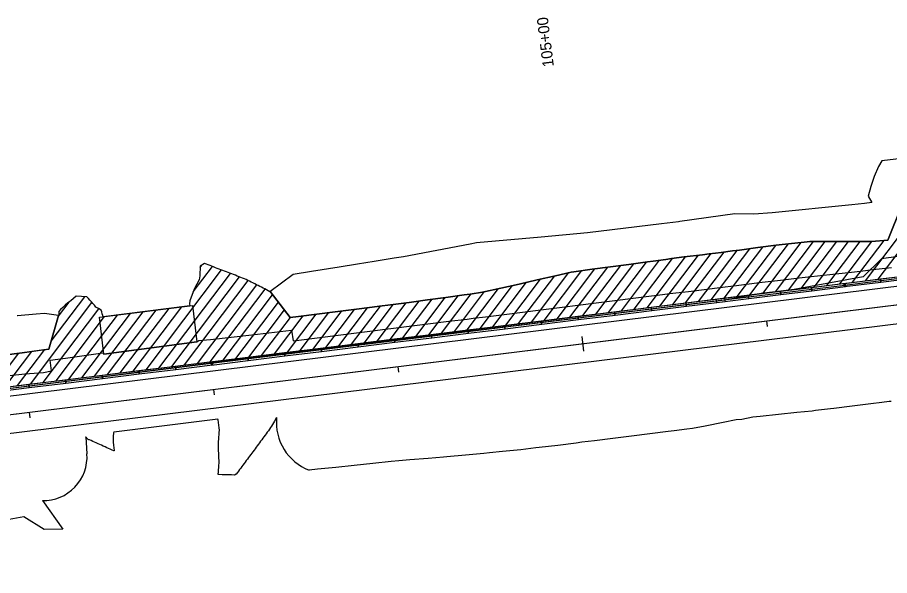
# Model space of a CAD drawing. Extents: x 1568809 to 1572786, y 728326 to 734907.
# Drawn here: x 1570478.4 to 1570947.9, y 732119 to 732419.2 of the extents above; entities that cross this region are included whole.
import ezdxf

# ---------------------------------------------------------------- set-up
doc = ezdxf.new("R2010")
doc.units = 0
for name, color, linetype in [('R_Horz Alg', 7, 'Continuous'), ('R_Horz Alg Annot', 7, 'Continuous'), ('R_MOT', 7, 'Continuous'), ('R_No Plot', 7, 'Continuous'), ('R_Striping', 7, 'Continuous')]:
    doc.layers.add(name, color=color, linetype=linetype)

msp = doc.modelspace()

# ---------------------------------------------------------------- linework, layer by layer
at = {"layer": 'R_Horz Alg'}
msp.add_line((1569774.69, 732119.01), (1571082.41, 732280.73), dxfattribs=at)
at = {"layer": 'R_Horz Alg Annot'}
for points in [[(1570882.23, 732252.95), (1570881.86, 732255.93)], [(1570782.13, 732247.63), (1570783.11, 732239.69)], [(1570683.74, 732228.41), (1570683.37, 732231.38)], [(1570584.5, 732216.13), (1570584.13, 732219.11)], [(1570485.25, 732203.86), (1570484.88, 732206.84)]]:
    msp.add_lwpolyline(points, dxfattribs=at)
at = {"layer": 'R_MOT'}
for p, q in [((1570934.91, 732277.61), (1570977.23, 732333.54)), ((1570941.83, 732278.46), (1570984.39, 732334.72)), ((1570851.91, 732267.34), (1570872.7, 732294.82)), ((1570858.83, 732268.2), (1570879.65, 732295.72)), ((1570865.75, 732269.05), (1570886.59, 732296.61)), ((1570872.66, 732269.91), (1570893.46, 732297.39)), ((1570879.58, 732270.76), (1570900.29, 732298.14)), ((1570886.5, 732271.62), (1570906.93, 732298.63)), ((1570893.41, 732272.47), (1570913.19, 732298.62)), ((1570900.33, 732273.33), (1570919.45, 732298.6)), ((1570907.25, 732274.19), (1570925.72, 732298.6)), ((1570914.16, 732275.04), (1570932, 732298.61)), ((1570921.08, 732275.9), (1570938.29, 732298.64)), ((1570928, 732276.75), (1570945.04, 732299.27)), ((1570817.33, 732263.07), (1570838.05, 732290.45)), ((1570824.25, 732263.92), (1570844.96, 732291.3)), ((1570831.16, 732264.78), (1570851.88, 732292.17)), ((1570838.08, 732265.63), (1570858.81, 732293.03)), ((1570845, 732266.49), (1570865.75, 732293.92)), ((1570572.97, 732271.56), (1570583.32, 732285.24)), ((1570576.69, 732284.75), (1570577.63, 732286)), ((1570782.75, 732258.79), (1570803.17, 732285.78)), ((1570789.66, 732259.64), (1570810.14, 732286.7)), ((1570796.58, 732260.5), (1570817.11, 732287.64)), ((1570803.5, 732261.35), (1570824.1, 732288.58)), ((1570810.41, 732262.21), (1570831.09, 732289.54)), ((1570547.58, 732229.71), (1570588.18, 732283.37)), ((1570554.5, 732230.56), (1570593.05, 732281.52)), ((1570755.08, 732255.37), (1570775.19, 732281.94)), ((1570762, 732256.22), (1570782.29, 732283.04)), ((1570768.91, 732257.08), (1570789.27, 732283.98)), ((1570775.83, 732257.93), (1570796.21, 732284.87)), ((1570561.42, 732231.42), (1570597.9, 732279.64)), ((1570568.33, 732232.27), (1570602.65, 732277.63)), ((1570734.33, 732252.8), (1570752.44, 732276.74)), ((1570741.25, 732253.66), (1570760.02, 732278.46)), ((1570748.17, 732254.51), (1570767.6, 732280.21)), ((1570575.25, 732233.13), (1570607.19, 732275.35)), ((1570582.17, 732233.98), (1570611.74, 732273.08)), ((1570713.58, 732250.23), (1570729.83, 732271.71)), ((1570720.5, 732251.09), (1570737.32, 732273.32)), ((1570727.42, 732251.95), (1570744.87, 732275.02)), ((1570898.53, 732273.11), (1570878.68, 732270.65)), ((1570496.52, 732245.08), (1570514.57, 732268.95)), ((1570858.95, 732267.21), (1570582.41, 732233.01)), ((1570589.08, 732234.84), (1570615.74, 732270.07)), ((1570679, 732245.96), (1570694.66, 732266.66)), ((1570685.92, 732246.81), (1570701.64, 732267.6)), ((1570692.83, 732247.67), (1570708.63, 732268.55)), ((1570699.75, 732248.52), (1570715.62, 732269.51)), ((1570706.67, 732249.38), (1570722.64, 732270.5)), ((1570878.68, 732270.65), (1570858.95, 732267.21)), ((1570485.33, 732222.01), (1570518.48, 732265.82)), ((1570492.25, 732222.86), (1570522.2, 732262.46)), ((1570500.38, 732258.47), (1570506.13, 732266.08)), ((1570526.83, 732227.14), (1570553.03, 732261.77)), ((1570533.75, 732227.99), (1570559.96, 732262.64)), ((1570540.67, 732228.85), (1570566.89, 732263.52)), ((1570596, 732235.69), (1570618.91, 732265.98)), ((1570602.92, 732236.55), (1570622.08, 732261.88)), ((1570644.42, 732241.68), (1570659.91, 732262.16)), ((1570651.33, 732242.54), (1570666.84, 732263.03)), ((1570658.25, 732243.39), (1570673.77, 732263.91)), ((1570665.17, 732244.25), (1570680.72, 732264.81)), ((1570672.08, 732245.1), (1570687.69, 732265.73)), ((1570499.17, 732223.72), (1570525.3, 732258.27)), ((1570506.08, 732224.57), (1570532.23, 732259.14)), ((1570513, 732225.43), (1570539.17, 732260.02)), ((1570519.92, 732226.28), (1570546.1, 732260.89)), ((1570609.83, 732237.4), (1570625.33, 732257.88)), ((1570616.75, 732238.26), (1570632.24, 732258.73)), ((1570623.67, 732239.11), (1570639.16, 732259.59)), ((1570630.58, 732239.97), (1570646.07, 732260.44)), ((1570637.5, 732240.83), (1570652.99, 732261.3)), ((1570464.58, 732219.44), (1570479.07, 732238.58)), ((1570471.5, 732220.3), (1570486.06, 732239.55)), ((1570478.42, 732221.15), (1570493.06, 732240.51)), ((1570582.65, 732233.03), (1570026.64, 732164.27))]:
    msp.add_line(p, q, dxfattribs=at)
for points in [[(1570943.03, 732278.6), (1570962.63, 732281.02), (1570962.87, 732279.06), (1570943.27, 732276.64)], [(1570905.82, 732274), (1570923.93, 732276.24), (1570924.17, 732274.28), (1570906.07, 732272.04)], [(1570923.43, 732276.17), (1570943.03, 732278.6), (1570943.27, 732276.64), (1570923.67, 732274.21)], [(1570871.83, 732269.8), (1570889.11, 732271.93), (1570889.35, 732269.97), (1570872.07, 732267.84)], [(1570889.11, 732271.93), (1570905.82, 732274), (1570906.07, 732272.04), (1570889.35, 732269.97)], [(1570838.22, 732265.64), (1570859.07, 732268.22), (1570859.31, 732266.25), (1570838.47, 732263.67)], [(1570854.72, 732267.68), (1570871.83, 732269.8), (1570872.07, 732267.84), (1570854.96, 732265.72)], [(1570522.49, 732257.91), (1570572.6, 732264.24), (1570574.94, 732244.65), (1570524.95, 732238.13)], [(1570799.84, 732260.9), (1570819.58, 732263.34), (1570819.83, 732261.36), (1570800.08, 732258.92)], [(1570819.58, 732263.34), (1570838.25, 732265.65), (1570838.49, 732263.67), (1570819.83, 732261.36)], [(1570760.35, 732256.01), (1570780.09, 732258.46), (1570780.34, 732256.48), (1570760.6, 732254.04)], [(1570780.09, 732258.46), (1570799.84, 732260.9), (1570800.08, 732258.92), (1570780.34, 732256.48)], [(1570720.87, 732251.13), (1570740.61, 732253.57), (1570740.85, 732251.6), (1570721.11, 732249.16)], [(1570740.61, 732253.57), (1570760.35, 732256.01), (1570760.6, 732254.04), (1570740.85, 732251.6)], [(1570681.38, 732246.25), (1570701.12, 732248.69), (1570701.37, 732246.71), (1570681.62, 732244.27)], [(1570701.12, 732248.69), (1570720.87, 732251.13), (1570721.11, 732249.16), (1570701.37, 732246.71)], [(1570641.89, 732241.36), (1570661.64, 732243.81), (1570661.88, 732241.83), (1570642.14, 732239.39)], [(1570661.64, 732243.81), (1570681.38, 732246.25), (1570681.62, 732244.27), (1570661.88, 732241.83)], [(1570602.41, 732236.48), (1570622.15, 732238.92), (1570622.39, 732236.95), (1570602.65, 732234.51)], [(1570622.15, 732238.92), (1570641.89, 732241.36), (1570642.14, 732239.39), (1570622.39, 732236.95)], [(1570563.39, 732231.66), (1570583.14, 732234.1), (1570583.38, 732232.12), (1570563.64, 732229.68)], [(1570582.66, 732234.04), (1570602.41, 732236.48), (1570602.65, 732234.51), (1570582.91, 732232.06)], [(1570523.91, 732226.77), (1570543.65, 732229.21), (1570543.89, 732227.24), (1570524.15, 732224.8)], [(1570543.65, 732229.21), (1570563.39, 732231.66), (1570563.64, 732229.68), (1570543.89, 732227.24)], [(1570484.42, 732221.89), (1570504.16, 732224.33), (1570504.41, 732222.36), (1570484.66, 732219.91)], [(1570504.16, 732224.33), (1570523.91, 732226.77), (1570524.15, 732224.8), (1570504.41, 732222.36)], [(1570464.68, 732219.45), (1570484.42, 732221.89), (1570484.66, 732219.91), (1570464.92, 732217.47)]]:
    msp.add_lwpolyline(points, close=True, dxfattribs=at)
at = {"layer": 'R_No Plot'}
for p, q in [((1570959.69, 732344.02), (1570943.76, 732342.05)), ((1570959.69, 732344.02), (1570943.76, 732342.05)), ((1570626.87, 732280.95), (1570626.87, 732280.95)), ((1570626.87, 732280.95), (1570626.87, 732280.95)), ((1570994.16, 732283.92), (1570920.86, 732274.74)), ((1570444.57, 732216.97), (1570896.54, 732272.86)), ((1570444.57, 732216.97), (1570896.54, 732272.86)), ((1570444.57, 732216.97), (1570896.54, 732272.86)), ((1570614.47, 732271.72), (1570625.18, 732257.87)), ((1570625.18, 732257.87), (1570614.47, 732271.72)), ((1570920.86, 732274.74), (1570851.15, 732266.26)), ((1570571.21, 732264.06), (1570524.53, 732258.17)), ((1570571.21, 732264.06), (1570524.53, 732258.17)), ((1570571.21, 732264.06), (1570524.53, 732258.17)), ((1570851.15, 732266.26), (1570582.65, 732233.03)), ((1570488.45, 732259.52), (1570478.36, 732258.66)), ((1570488.45, 732259.52), (1570478.36, 732258.66)), ((1570495.29, 732240.82), (1570500.49, 732258.87)), ((1570500.49, 732258.87), (1570495.29, 732240.82)), ((1570625.95, 732250.99), (1570626.75, 732245.23)), ((1570496.73, 732229.18), (1570495.95, 732234.82)), ((1570582.65, 732233.03), (1570026.64, 732164.27)), ((1570586.31, 732203.09), (1570530.21, 732196.15)), ((1570515.16, 732193.67), (1570515.78, 732184.45)), ((1570491.78, 732159.29), (1570502.74, 732143.97))]:
    msp.add_line(p, q, dxfattribs=at)
for points in [[(1570943.76, 732342.05), (1570942.01, 732338.94), (1570939.63, 732333.61), (1570937.73, 732328.34), (1570936.33, 732323.12), (1570938.27, 732319.7), (1570934.41, 732319.19), (1570927.55, 732318.4), (1570884.75, 732314.03)], [(1570943.76, 732342.05), (1570942.01, 732338.94), (1570939.63, 732333.61), (1570937.73, 732328.34), (1570936.33, 732323.12), (1570938.27, 732319.7), (1570934.41, 732319.19), (1570927.55, 732318.4), (1570884.75, 732314.03)], [(1570947.01, 732299.46), (1570954.72, 732318.58), (1570965.7, 732331.64)], [(1570965.7, 732331.64), (1570954.72, 732318.58), (1570947.01, 732299.46)], [(1570884.75, 732314.03), (1570874.75, 732313.44), (1570864.65, 732313.59), (1570834.95, 732309.36), (1570834.3, 732309.28), (1570825.03, 732308.11), (1570785.3, 732303.41), (1570760.4, 732301.07), (1570725.53, 732297.92), (1570722.17, 732297.17), (1570686.15, 732290.44), (1570681.2, 732289.72), (1570670.37, 732287.85), (1570661.45, 732286.41), (1570651.57, 732284.86), (1570636.74, 732282.54), (1570626.87, 732280.96)], [(1570884.75, 732314.03), (1570874.75, 732313.44), (1570864.65, 732313.59), (1570834.95, 732309.36), (1570834.3, 732309.28), (1570825.03, 732308.11), (1570785.3, 732303.41), (1570760.4, 732301.07), (1570725.53, 732297.92), (1570722.17, 732297.17), (1570686.15, 732290.44), (1570681.2, 732289.72), (1570670.37, 732287.85), (1570661.45, 732286.41), (1570651.57, 732284.86), (1570636.74, 732282.54), (1570626.87, 732280.96)], [(1570625.18, 732257.87), (1570629.65, 732258.41), (1570639.57, 732259.64), (1570649.5, 732260.87), (1570659.42, 732262.1), (1570669.34, 732263.35), (1570673.34, 732263.85), (1570679.26, 732264.62), (1570689.18, 732265.93), (1570699.09, 732267.25), (1570709, 732268.6), (1570718.91, 732269.96), (1570722.03, 732270.4), (1570728.79, 732271.49), (1570738.61, 732273.6), (1570748.41, 732275.82), (1570758.21, 732278.05), (1570768.01, 732280.3), (1570776.48, 732282.24), (1570777.82, 732282.43), (1570787.73, 732283.78), (1570797.65, 732285.06), (1570807.56, 732286.36), (1570817.48, 732287.69), (1570820.6, 732288.11), (1570827.39, 732289.03), (1570830.51, 732289.46), (1570837.3, 732290.36), (1570847.22, 732291.58), (1570850.84, 732292.03), (1570854.25, 732292.46), (1570857.15, 732292.82), (1570863.25, 732293.6), (1570867.06, 732294.09), (1570876.98, 732295.38), (1570886.9, 732296.65), (1570895, 732297.57), (1570896.84, 732297.77), (1570903.45, 732298.48), (1570904.94, 732298.64), (1570906.81, 732298.64), (1570916.89, 732298.61), (1570926.96, 732298.6), (1570933.04, 732298.62), (1570937.04, 732298.63), (1570938.2, 732298.63), (1570947.01, 732299.46)], [(1570947.01, 732299.46), (1570938.2, 732298.63), (1570937.04, 732298.63), (1570933.04, 732298.62), (1570926.96, 732298.6), (1570916.89, 732298.61), (1570906.81, 732298.64), (1570904.94, 732298.64), (1570903.45, 732298.48), (1570896.84, 732297.77), (1570895, 732297.57), (1570886.9, 732296.65), (1570876.98, 732295.38), (1570867.06, 732294.09), (1570863.25, 732293.6), (1570857.15, 732292.82), (1570854.25, 732292.46), (1570850.84, 732292.03), (1570847.22, 732291.58), (1570837.3, 732290.36), (1570830.51, 732289.46), (1570827.39, 732289.03), (1570820.6, 732288.11), (1570817.48, 732287.69), (1570807.56, 732286.36), (1570797.65, 732285.06), (1570787.73, 732283.78), (1570777.82, 732282.43), (1570776.48, 732282.24), (1570768.01, 732280.3), (1570758.21, 732278.05), (1570748.41, 732275.82), (1570738.61, 732273.6), (1570728.79, 732271.49), (1570722.03, 732270.4), (1570718.91, 732269.96), (1570709, 732268.6), (1570699.09, 732267.25), (1570689.18, 732265.93), (1570679.26, 732264.62), (1570673.34, 732263.85), (1570669.34, 732263.35), (1570659.42, 732262.1), (1570649.5, 732260.87), (1570639.57, 732259.64), (1570629.65, 732258.41), (1570625.18, 732257.87)], [(1571080.52, 732296.05), (1570973.02, 732293.44), (1570943.63, 732289.39), (1570933.75, 732279.73), (1570896.54, 732272.86), (1570444.72, 732215.92), (1570444.57, 732216.97), (1570302.77, 732199.43)], [(1571080.52, 732296.05), (1570973.02, 732293.44), (1570943.63, 732289.39), (1570933.75, 732279.73), (1570896.54, 732272.86), (1570444.72, 732215.92), (1570444.57, 732216.97), (1570302.77, 732199.43)], [(1570896.54, 732272.86), (1570943.54, 732278.67), (1570975.29, 732282.6), (1571080.57, 732295.62)], [(1570896.54, 732272.86), (1570943.54, 732278.67), (1570975.29, 732282.6), (1571080.57, 732295.62)], [(1570896.54, 732272.86), (1570943.54, 732278.67), (1570975.29, 732282.6), (1571080.57, 732295.62)], [(1570576.7, 732285.46), (1570576.67, 732283.72), (1570576.61, 732282.02), (1570576.51, 732280.27), (1570576.11, 732278.13), (1570573.72, 732273.44), (1570572.4, 732270.12), (1570571.09, 732266.81), (1570571.05, 732265.13), (1570571.21, 732264.06)], [(1570576.7, 732285.46), (1570576.67, 732283.72), (1570576.61, 732282.02), (1570576.51, 732280.27), (1570576.11, 732278.13), (1570573.72, 732273.44), (1570572.4, 732270.12), (1570571.09, 732266.81), (1570571.05, 732265.13), (1570571.21, 732264.06)], [(1570576.7, 732285.46), (1570576.67, 732283.72), (1570576.61, 732282.02), (1570576.51, 732280.27), (1570576.11, 732278.13), (1570573.72, 732273.44), (1570572.4, 732270.12), (1570571.09, 732266.81), (1570571.05, 732265.13), (1570571.21, 732264.06)], [(1570626.87, 732280.95), (1570614.31, 732271.6), (1570613.4, 732272.21), (1570612.45, 732272.73), (1570611.56, 732273.17), (1570610.65, 732273.63), (1570609.73, 732274.08), (1570608.82, 732274.54), (1570607.91, 732275), (1570607, 732275.45), (1570606.08, 732275.91), (1570605.17, 732276.37), (1570604.26, 732276.82), (1570603.35, 732277.28), (1570602.43, 732277.73), (1570601.52, 732278.19), (1570600.57, 732278.6), (1570599.6, 732278.98), (1570598.63, 732279.36), (1570597.66, 732279.74), (1570596.69, 732280.12), (1570595.71, 732280.5), (1570594.74, 732280.88), (1570593.76, 732281.25), (1570592.78, 732281.62), (1570591.81, 732281.99), (1570590.83, 732282.36), (1570589.85, 732282.74), (1570588.87, 732283.11), (1570587.89, 732283.48), (1570586.92, 732283.85), (1570585.94, 732284.23), (1570584.96, 732284.6), (1570583.99, 732284.98), (1570583.02, 732285.36), (1570582.04, 732285.73), (1570581.07, 732286.11), (1570580.09, 732286.49), (1570579.12, 732286.86), (1570576.7, 732285.46)], [(1570626.87, 732280.95), (1570614.31, 732271.6), (1570613.4, 732272.21), (1570612.45, 732272.73), (1570611.56, 732273.17), (1570610.65, 732273.63), (1570609.73, 732274.08), (1570608.82, 732274.54), (1570607.91, 732275), (1570607, 732275.45), (1570606.08, 732275.91), (1570605.17, 732276.37), (1570604.26, 732276.82), (1570603.35, 732277.28), (1570602.43, 732277.73), (1570601.52, 732278.19), (1570600.57, 732278.6), (1570599.6, 732278.98), (1570598.63, 732279.36), (1570597.66, 732279.74), (1570596.69, 732280.12), (1570595.71, 732280.5), (1570594.74, 732280.88), (1570593.76, 732281.25), (1570592.78, 732281.62), (1570591.81, 732281.99), (1570590.83, 732282.36), (1570589.85, 732282.74), (1570588.87, 732283.11), (1570587.89, 732283.48), (1570586.92, 732283.85), (1570585.94, 732284.23), (1570584.96, 732284.6), (1570583.99, 732284.98), (1570583.02, 732285.36), (1570582.04, 732285.73), (1570581.07, 732286.11), (1570580.09, 732286.49), (1570579.12, 732286.86), (1570576.7, 732285.46)], [(1570614.47, 732271.72), (1570614.31, 732271.6), (1570613.4, 732272.21), (1570612.45, 732272.73), (1570611.56, 732273.17), (1570610.65, 732273.63), (1570609.73, 732274.08), (1570608.82, 732274.54), (1570607.91, 732275), (1570607, 732275.45), (1570606.08, 732275.91), (1570605.17, 732276.37), (1570604.26, 732276.82), (1570603.35, 732277.28), (1570602.43, 732277.73), (1570601.52, 732278.19), (1570600.57, 732278.6), (1570599.6, 732278.98), (1570598.63, 732279.36), (1570597.66, 732279.74), (1570596.69, 732280.12), (1570595.71, 732280.5), (1570594.74, 732280.88), (1570593.76, 732281.25), (1570592.78, 732281.62), (1570591.81, 732281.99), (1570590.83, 732282.36), (1570589.85, 732282.74), (1570588.87, 732283.11), (1570587.89, 732283.48), (1570586.92, 732283.85), (1570585.94, 732284.23), (1570584.96, 732284.6), (1570583.99, 732284.98), (1570583.02, 732285.36), (1570582.04, 732285.73), (1570581.07, 732286.11), (1570580.09, 732286.49), (1570579.12, 732286.86), (1570576.7, 732285.46)], [(1570626.75, 732245.23), (1570631.21, 732245.78), (1570641.13, 732247.04), (1570651.05, 732248.3), (1570660.97, 732249.56), (1570670.89, 732250.83), (1570674.89, 732251.34), (1570680.81, 732252.1), (1570690.74, 732253.31), (1570700.66, 732254.53), (1570710.59, 732255.76), (1570720.51, 732256.99), (1570723.64, 732257.38), (1570730.43, 732258.24), (1570740.36, 732259.48), (1570750.28, 732260.73), (1570760.2, 732261.98), (1570770.12, 732263.23), (1570771.57, 732263.42), (1570780.04, 732264.5), (1570789.96, 732265.73), (1570799.89, 732266.95), (1570809.81, 732268.17), (1570819.74, 732269.41), (1570822.86, 732269.79), (1570829.66, 732270.64), (1570832.79, 732271.03), (1570839.58, 732271.87), (1570849.51, 732273.1), (1570856.54, 732273.97), (1570859.43, 732274.32), (1570865.54, 732275.07), (1570869.36, 732275.54), (1570879.28, 732276.78), (1570889.21, 732277.97), (1570899.15, 732279.08), (1570905.76, 732279.81), (1570909.09, 732280.19), (1570919.03, 732281.31), (1570928.96, 732282.43), (1570934.95, 732283.1), (1570938.9, 732283.55), (1570948.84, 732284.68)], [(1570510.02, 732269.19), (1570508.53, 732267.99), (1570507.04, 732266.8), (1570505.55, 732265.61), (1570504.14, 732264.43), (1570502.81, 732263.26), (1570501.48, 732262.08), (1570500.71, 732260.98), (1570500.6, 732259.96), (1570500.5, 732258.94), (1570492.93, 732259.89), (1570488.45, 732259.52)], [(1570510.02, 732269.19), (1570508.53, 732267.99), (1570507.04, 732266.8), (1570505.55, 732265.61), (1570504.14, 732264.43), (1570502.81, 732263.26), (1570501.48, 732262.08), (1570500.71, 732260.98), (1570500.6, 732259.96), (1570500.5, 732258.94), (1570492.93, 732259.89), (1570488.45, 732259.52)], [(1570510.02, 732269.19), (1570508.53, 732267.99), (1570507.04, 732266.8), (1570505.55, 732265.61), (1570504.14, 732264.43), (1570502.81, 732263.26), (1570501.48, 732262.08), (1570500.71, 732260.98), (1570500.6, 732259.96), (1570500.49, 732258.87)], [(1570524.53, 732258.17), (1570524.32, 732258.86), (1570524.04, 732259.83), (1570523.76, 732260.81), (1570523.47, 732261.78), (1570521.94, 732262.6), (1570520.62, 732263.44), (1570519.81, 732264.35), (1570518.99, 732265.26), (1570518.18, 732266.16), (1570517.36, 732267.07), (1570516.55, 732267.98), (1570515.73, 732268.88), (1570510.02, 732269.19)], [(1570524.53, 732258.17), (1570524.32, 732258.86), (1570524.04, 732259.83), (1570523.76, 732260.81), (1570523.47, 732261.78), (1570521.94, 732262.6), (1570520.62, 732263.44), (1570519.81, 732264.35), (1570518.99, 732265.26), (1570518.18, 732266.16), (1570517.36, 732267.07), (1570516.55, 732267.98), (1570515.73, 732268.88), (1570510.02, 732269.19)], [(1570524.53, 732258.17), (1570524.32, 732258.86), (1570524.04, 732259.83), (1570523.76, 732260.81), (1570523.47, 732261.78), (1570521.94, 732262.6), (1570520.62, 732263.44), (1570519.81, 732264.35), (1570518.99, 732265.26), (1570518.18, 732266.16), (1570517.36, 732267.07), (1570516.55, 732267.98), (1570515.73, 732268.88), (1570510.02, 732269.19)], [(1570575.94, 732245.46), (1570582.24, 732245.98), (1570604.61, 732248.54), (1570625.95, 732250.99)], [(1570524.31, 732238.82), (1570524.95, 732238.13), (1570574.94, 732244.65), (1570575.94, 732245.46)], [(1570471.02, 732237.48), (1570480.93, 732238.84), (1570490.83, 732240.2), (1570495.29, 732240.82)], [(1570495.29, 732240.82), (1570480.93, 732238.84), (1570471.02, 732237.48)], [(1570495.95, 732234.82), (1570504.17, 732235.97), (1570519.32, 732238.1), (1570524.31, 732238.82)], [(1570472.39, 732226.37), (1570482.32, 732227.56), (1570492.32, 732228.23), (1570496.73, 732229.18)], [(1570948.82, 732212.71), (1570947.68, 732212.58), (1570943.73, 732212.12), (1570937.75, 732211.42), (1570927.83, 732210.16), (1570917.91, 732208.87), (1570916.07, 732208.65), (1570907.98, 732207.71), (1570906.14, 732207.49), (1570898.03, 732206.65), (1570888.09, 732205.57), (1570878.14, 732204.57), (1570874.3, 732204.19), (1570868.27, 732202.91), (1570865.34, 732202.73), (1570858.38, 732201.36), (1570848.54, 732199.42), (1570841.81, 732198.08), (1570838.67, 732197.78), (1570831.88, 732196.89), (1570828.75, 732196.51), (1570818.82, 732195.31), (1570808.91, 732194.01), (1570798.98, 732192.79), (1570789.06, 732191.55), (1570782.26, 732190.7), (1570779.14, 732190.27), (1570769.24, 732188.89), (1570759.28, 732187.92), (1570757.45, 732187.69), (1570749.36, 732186.67), (1570739.41, 732185.65), (1570732.58, 732185.04), (1570729.45, 732184.71), (1570719.5, 732183.71), (1570709.53, 732182.85), (1570707.68, 732182.71), (1570699.55, 732182.05), (1570689.58, 732181.22), (1570683.62, 732180.71), (1570679.61, 732180.37), (1570669.66, 732179.32), (1570659.71, 732178.26), (1570649.77, 732177.21), (1570639.82, 732176.16), (1570635.41, 732175.7)], [(1570586.45, 732173.28), (1570586.47, 732173.55), (1570586.56, 732174.75), (1570586.65, 732175.94), (1570586.74, 732177.14), (1570586.83, 732178.34), (1570586.92, 732179.53), (1570586.89, 732180.83), (1570586.84, 732182.13), (1570586.79, 732183.44), (1570586.74, 732184.75), (1570586.69, 732186.05), (1570586.65, 732187.36), (1570586.6, 732188.67), (1570586.6, 732189.93), (1570586.69, 732191.13), (1570586.78, 732192.33), (1570586.87, 732193.53), (1570586.96, 732194.73), (1570587.04, 732195.93), (1570587.13, 732197.12), (1570586.97, 732198.52), (1570586.77, 732199.95), (1570586.56, 732201.38), (1570586.35, 732202.81), (1570586.31, 732203.09)], [(1570617.86, 732203.94), (1570616.67, 732201.99), (1570616.15, 732201.13), (1570615.62, 732200.27), (1570615.1, 732199.41), (1570614.58, 732198.55), (1570614.04, 732197.7), (1570613.44, 732196.9), (1570612.85, 732196.09), (1570612.25, 732195.29), (1570611.66, 732194.48), (1570611.07, 732193.68), (1570610.47, 732192.87), (1570609.88, 732192.07), (1570609.28, 732191.26), (1570608.69, 732190.46), (1570608.09, 732189.66), (1570607.5, 732188.85), (1570606.9, 732188.05), (1570606.31, 732187.24), (1570605.72, 732186.44), (1570605.12, 732185.63), (1570604.52, 732184.83), (1570603.93, 732184.03), (1570603.33, 732183.22), (1570602.73, 732182.42), (1570602.14, 732181.62), (1570601.54, 732180.82), (1570600.94, 732180.01), (1570600.35, 732179.21), (1570599.76, 732178.4), (1570599.16, 732177.6), (1570598.57, 732176.79), (1570597.98, 732175.98), (1570597.39, 732175.18), (1570596.79, 732174.37), (1570596.2, 732173.57), (1570595.21, 732173.07), (1570593.54, 732173.11), (1570591.86, 732173.15), (1570590.18, 732173.19), (1570588.51, 732173.23), (1570586.83, 732173.27), (1570586.45, 732173.28)], [(1570530.21, 732196.15), (1570530.15, 732195.78), (1570529.84, 732193.74), (1570529.83, 732192.11), (1570529.97, 732190.66), (1570530.11, 732189.21), (1570530.24, 732187.76), (1570530.38, 732186.3), (1570530.4, 732186)], [(1570530.4, 732186), (1570530.21, 732186.09), (1570529.27, 732186.51), (1570528.33, 732186.94), (1570527.4, 732187.36), (1570526.46, 732187.78), (1570525.52, 732188.21), (1570524.58, 732188.63), (1570523.65, 732189.06), (1570522.71, 732189.48), (1570521.77, 732189.9), (1570520.83, 732190.33), (1570519.9, 732190.75), (1570518.96, 732191.17), (1570518.02, 732191.6), (1570517.08, 732191.96), (1570516.78, 732192.08), (1570516.49, 732192.24), (1570516.21, 732192.43), (1570515.94, 732192.65), (1570515.68, 732192.9), (1570515.45, 732193.18), (1570515.25, 732193.49), (1570515.16, 732193.67)], [(1570502.74, 732143.97), (1570492.69, 732143.73), (1570481.76, 732150.66), (1570471.92, 732148.74)]]:
    msp.add_lwpolyline(points, dxfattribs=at)
for centre, radius, start, end in [((1570626.88, 732280.94), 0.0141, 112.2326, 158.4868), ((1570478.24, 732258.55), 0.16, 42.7401, 93.2038), ((1570478.24, 732258.55), 0.16, 42.7401, 93.2038), ((1570645.26, 732201.4), 27.52, 174.6978, 249.0333), ((1570492.26, 732182.86), 23.57, 268.828, 3.8631)]:
    msp.add_arc(centre, radius, start, end, dxfattribs=at)
msp.add_ellipse((1570626.88, 732280.94), major_axis=(0.0131, 0.0053), ratio=0.999998, start_param=1.570376, end_param=2.377663, dxfattribs=at)
at = {"layer": 'R_Striping'}
for p, q in [((1570027.14, 732160.3), (1571081.18, 732290.66)), ((1570028.36, 732150.38), (1571082.41, 732280.73)), ((1570029.59, 732140.45), (1571083.64, 732270.81))]:
    msp.add_line(p, q, dxfattribs=at)

# ---------------------------------------------------------------- texts
at = {"layer": 'R_Horz Alg Annot'}
msp.add_text('105+00', height=6, rotation=97.05, dxfattribs=at).set_placement((1570767.18, 732392.89))

doc.saveas('drawing.dxf')
